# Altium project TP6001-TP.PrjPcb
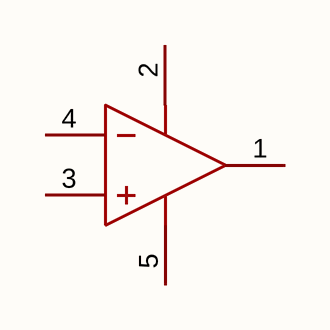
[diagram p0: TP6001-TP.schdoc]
1 sheet, 1 parts. Net scope: global (net labels, ports and power ports of the same name join across sheets).

## Sheet TP6001-TP.schdoc
size 127 x 101 mm

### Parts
U?  tp6001-tp  [SOT-23-5_L3.0-W1.7-P0.95-LS2.8-BL]  (value not drawn)

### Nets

Not connected (* = marked no-connect by the designer): U? 1(OUT) 2(+VS) 3(+IN) 4(-IN) 5(-VS)

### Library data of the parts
U? = tp6001-tp: Manufacturer: TECH PUBLIC(台舟); AddInBom: yes; ModelId: 0a2a1b8f50944f73965918ad6e5fe167; ModelName: SOT-23-5_L2.9-W1.6-H1.1-LS2.8-P0.95; ModelTransform: 118.60433,114.173,0,90,0,0,0.0005,0.0005,0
